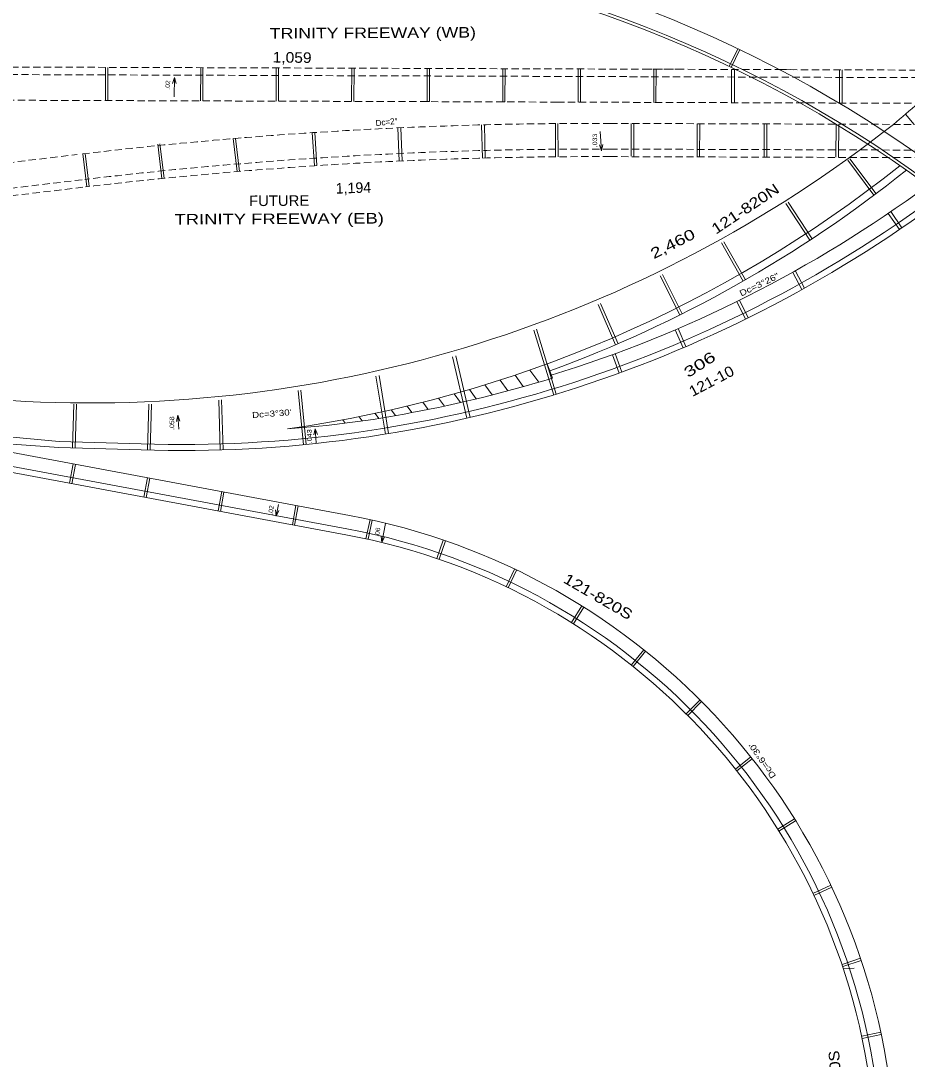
# Model space of a CAD drawing. Extents: x 2354993 to 2372084, y 6966390 to 6990057.
# Drawn here: x 2363006 to 2364180, y 6976742 to 6978118 of the extents above; entities that cross this region are included whole.
import ezdxf
from ezdxf.enums import TextEntityAlignment as Align

# ---------------------------------------------------------------- set-up
doc = ezdxf.new("R2010")
doc.units = 0
doc.header["$LTSCALE"] = 3.2
doc.linetypes.add('MEDIUM_DASHED', pattern=[4.5, 3, -1.5])
for name, color, linetype, lineweight in [('12', 7, 'Continuous', 13), ('13', 7, 'Continuous', 13), ('17', 7, 'Continuous', 13), ('19', 7, 'Continuous', 13), ('23', 7, 'Continuous', 13), ('5', 7, 'Continuous', 13), ('61', 7, 'Continuous', 13), ('7', 7, 'Continuous', 13)]:
    doc.layers.add(name, color=color, linetype=linetype, lineweight=lineweight)

msp = doc.modelspace()

# ---------------------------------------------------------------- linework, layer by layer
at = {"layer": '12'}
for p, q in [((2363943.892, 6978057.276), (2363955.166, 6978080.703)), ((2363946.596, 6978055.978), (2363957.869, 6978079.405)), ((2363117.932, 6978011.954), (2363118.08, 6978055.955)), ((2363120.931, 6978011.944), (2363121.079, 6978055.945)), ((2363244.03, 6978055.53), (2363243.881, 6978011.53)), ((2363247.029, 6978055.52), (2363246.881, 6978011.52)), ((2363344.03, 6978055.193), (2363343.881, 6978011.193)), ((2363347.029, 6978055.183), (2363346.88, 6978011.182)), ((2363444.028, 6978054.856), (2363443.88, 6978010.855)), ((2363447.028, 6978054.845), (2363446.879, 6978010.845)), ((2363544.028, 6978054.518), (2363543.88, 6978010.518)), ((2363547.027, 6978054.508), (2363546.879, 6978010.507)), ((2363644.027, 6978054.181), (2363643.878, 6978010.18)), ((2363647.026, 6978054.17), (2363646.878, 6978010.17)), ((2363743.878, 6978009.844), (2363744.027, 6978053.844)), ((2363747.026, 6978053.834), (2363744.027, 6978053.844)), ((2363746.877, 6978009.833), (2363747.026, 6978053.834)), ((2363844.027, 6978053.507), (2363843.878, 6978009.506)), ((2363847.026, 6978053.496), (2363846.877, 6978009.496)), ((2363947.025, 6978053.159), (2363946.876, 6978009.159)), ((2363951.025, 6978053.145), (2363950.876, 6978009.145)), ((2363546.879, 6978010.507), (2363543.88, 6978010.518)), ((2363643.878, 6978010.18), (2363646.878, 6978010.17)), ((2364046.876, 6978008.821), (2364043.877, 6978008.831)), ((2364177.285, 6977993.799), (2364188.905, 6977980.343)), ((2364154.496, 6977862.559), (2364169.167, 6977841.094)), ((2364157.799, 6977864.816), (2364172.47, 6977843.351)), ((2364028.251, 6977784.188), (2364040.203, 6977761.604)), ((2364031.787, 6977786.059), (2364043.738, 6977763.474)), ((2363957.495, 6977747.502), (2363969.04, 6977724.206)), ((2363953.911, 6977745.726), (2363965.456, 6977722.43)), ((2363872.441, 6977708.284), (2363882.716, 6977684.401)), ((2363876.115, 6977709.865), (2363886.39, 6977685.981)), ((2363789.168, 6977675.319), (2363798.086, 6977650.897)), ((2363792.926, 6977676.691), (2363801.844, 6977652.269))]:
    msp.add_line(p, q, dxfattribs=at)
at = {"layer": '17'}
for p, q in [((2363213.75, 6977595.134), (2363216.528, 6977587.302)), ((2363395.689, 6977577.258), (2363398.467, 6977569.426)), ((2363343.757, 6977461.575), (2363343.114, 6977469.86)), ((2363483.762, 6977426.498), (2363483.119, 6977434.783))]:
    msp.add_line(p, q, dxfattribs=at)
for points in [[(2363214.946, 6977576.421), (2363213.75, 6977595.134), (2363211.989, 6977587.01)], [(2363396.885, 6977558.545), (2363395.689, 6977577.258), (2363393.928, 6977569.134)], [(2363346.852, 6977476.819), (2363343.757, 6977461.575), (2363347.575, 6977468.951)], [(2363488.892, 6977451.764), (2363483.762, 6977426.498), (2363487.58, 6977433.874)]]:
    msp.add_lwpolyline(points, dxfattribs=at)
at = {"layer": '19'}
for p, q in [((2363209.28, 6978042.726), (2363211.427, 6978034.696)), ((2363774.866, 6977945.446), (2363772.047, 6977953.265))]:
    msp.add_line(p, q, dxfattribs=at)
for points in [[(2363208.858, 6978016.946), (2363209.28, 6978042.726), (2363206.875, 6978034.776)], [(2363773.102, 6977971.168), (2363774.866, 6977945.446), (2363776.589, 6977953.571)]]:
    msp.add_lwpolyline(points, dxfattribs=at)
at = {"layer": '23'}
msp.add_line((2364095.179, 6976861.879), (2364109.155, 6976862.696), dxfattribs=at)
at = {"layer": '5', "linetype": 'MEDIUM_DASHED'}
for p, q in [((2363881.241, 6978053.379), (2362958.761, 6978056.492)), ((2364028.375, 6978052.885), (2363826.78, 6978053.565)), ((2364725.162, 6978050.535), (2364010.427, 6978052.946)), ((2363836.954, 6978043.529), (2362958.726, 6978046.492)), ((2364037.424, 6978042.853), (2363803.238, 6978043.643)), ((2364727.772, 6978040.524), (2364029.265, 6978042.88)), ((2362958.612, 6978012.492), (2363716.295, 6978009.935)), ((2363715.928, 6978009.937), (2364096.849, 6978008.653)), ((2364089.244, 6978008.678), (2364762.775, 6978006.406)), ((2363786.467, 6977981.699), (2365246.775, 6977976.776)), ((2362801.702, 6977907.216), (2363080.587, 6977940.529)), ((2363786.352, 6977947.7), (2365246.66, 6977942.776)), ((2363786.319, 6977937.7), (2365246.626, 6977932.776)), ((2362805.732, 6977873.455), (2363090.394, 6977907.458)), ((2362806.918, 6977863.526), (2363091.58, 6977897.529))]:
    msp.add_line(p, q, dxfattribs=at)
at = {"layer": '5'}
for p, q in [((2363680.035, 6977654.95), (2363691.558, 6977638.881)), ((2363702.768, 6977663.093), (2363709.649, 6977644.314)), ((2363640.373, 6977641.618), (2363650.618, 6977627.332)), ((2363660.284, 6977648.172), (2363671.172, 6977632.99)), ((2363579.665, 6977623.315), (2363587.923, 6977611.799)), ((2363600.066, 6977629.186), (2363608.996, 6977616.733)), ((2363620.301, 6977635.288), (2363629.893, 6977621.912)), ((2363538.357, 6977612.279), (2363545.24, 6977602.681)), ((2363559.096, 6977617.678), (2363566.672, 6977607.113)), ((2363475.093, 6977597.54), (2363479.821, 6977590.946)), ((2363496.358, 6977602.206), (2363501.818, 6977594.592)), ((2363517.445, 6977607.12), (2363523.623, 6977598.505)), ((2363432.015, 6977588.971), (2363435.238, 6977584.476)), ((2363453.646, 6977593.127), (2363457.63, 6977587.572)), ((2363056.715, 6977560.454), (2362953.628, 6977569.627)), ((2363436.244, 6977436.841), (2362775.531, 6977559.85)), ((2363437.708, 6977444.706), (2362776.995, 6977567.714)), ((2362952.814, 6977559.66), (2363056.326, 6977552.462)), ((2363165.231, 6977557.069), (2363056.715, 6977560.454)), ((2363441.003, 6977462.402), (2362950.662, 6977553.691)), ((2363164.981, 6977549.073), (2363056.326, 6977552.462))]:
    msp.add_line(p, q, dxfattribs=at)
for centre, radius, start, end in [((2363244.672, 6976597.082), 1645.014, 38.12295, 103.3303), ((2363244.672, 6976597.082), 1623.014, 38.12295, 103.3303), ((2363244.672, 6976597.082), 1619.014, 38.12295, 103.3303), ((2363127.192, 6979233.99), 1625.022, 309.51957, 311.04051), ((2363097.562, 6979328.645), 1717.302, 266.49182, 308.27248), ((2363127.192, 6979233.99), 1673.022, 277.96238, 308.55257), ((2363127.192, 6979233.99), 1683.022, 290.12282, 308.67239), ((2363217.727, 6979240.251), 1666, 287.12386, 306.40449), ((2363217.727, 6979240.251), 1684, 268.21361, 306.58945), ((2363217.727, 6979240.251), 1692, 268.21361, 306.66787), ((2363215.437, 6979250.646), 1680.639, 280.56637, 287.10131), ((2363265.996, 6978936.147), 1362.225, 273.91247, 280.90154), ((2363278.934, 6976591.886), 885.473, 4.66908, 79.45368), ((2363278.934, 6976591.886), 867.473, 4.66908, 79.45368), ((2363278.934, 6976591.886), 859.473, 4.66908, 79.45368)]:
    msp.add_arc(centre, radius, start, end, dxfattribs=at)
at = {"layer": '5', "linetype": 'MEDIUM_DASHED'}
for radius in [5739.578, 5705.578, 5695.578]:
    msp.add_arc((2363767.116, 6972242.154), radius, 89.80682, 96.81171, dxfattribs=at)
at = {"layer": '61'}
for p, q in [((2364090.028, 6978052.677), (2364089.879, 6978008.658)), ((2364093.528, 6978052.666), (2364093.379, 6978008.646)), ((2363713.621, 6977981.484), (2363714.004, 6977937.486)), ((2363717.121, 6977981.514), (2363717.504, 6977937.516)), ((2363814.093, 6977981.606), (2363813.947, 6977938.091)), ((2363817.593, 6977981.595), (2363817.447, 6977938.079)), ((2363901.359, 6977981.312), (2363901.209, 6977936.808)), ((2363904.859, 6977981.3), (2363904.709, 6977936.797)), ((2363990.363, 6977981.289), (2363990.213, 6977937.012)), ((2363993.862, 6977981.277), (2363993.713, 6977937)), ((2363394.559, 6977925.534), (2363391.681, 6977969.44)), ((2363397.837, 6977925.748), (2363394.985, 6977969.656)), ((2363506.94, 6977931.787), (2363504.93, 6977975.741)), ((2363510.86, 6977931.964), (2363508.88, 6977975.92)), ((2363617.208, 6977935.759), (2363616.05, 6977979.744)), ((2363620.771, 6977935.852), (2363619.64, 6977979.837)), ((2364085.307, 6977980.692), (2364085.159, 6977936.968)), ((2364088.807, 6977980.68), (2364088.659, 6977936.957)), ((2363192.564, 6977908.679), (2363187.108, 6977954.356)), ((2363195.55, 6977908.98), (2363190.087, 6977954.711)), ((2363292.347, 6977917.91), (2363286.922, 6977961.609)), ((2363295.34, 6977918.159), (2363289.913, 6977961.86)), ((2363093.163, 6977897.717), (2363087.932, 6977941.511)), ((2363096.142, 6977898.072), (2363090.911, 6977941.866)), ((2364100.733, 6977932.869), (2364135.48, 6977886.429)), ((2364103.535, 6977934.966), (2364138.28, 6977888.529)), ((2364018.816, 6977875.423), (2364050.64, 6977826.933)), ((2364021.742, 6977877.343), (2364053.564, 6977828.856)), ((2363933.77, 6977823.27), (2363962.558, 6977772.919)), ((2363936.808, 6977825.007), (2363965.595, 6977774.659)), ((2363852.499, 6977779.81), (2363878.497, 6977727.967)), ((2363855.628, 6977781.379), (2363881.627, 6977729.533)), ((2363770.355, 6977741.659), (2363793.423, 6977688.448)), ((2363773.566, 6977743.051), (2363796.636, 6977689.837)), ((2363711.411, 6977621.871), (2363685.022, 6977707.712)), ((2363714.929, 6977622.952), (2363688.481, 6977708.981)), ((2363596.2, 6977591.123), (2363577.5, 6977672.606)), ((2363600.62, 6977592.144), (2363581.647, 6977673.808)), ((2363488.545, 6977570.065), (2363476.092, 6977646.865)), ((2363492.823, 6977570.764), (2363480.136, 6977647.759)), ((2363380.001, 6977556.05), (2363373.1, 6977627.681)), ((2363383.787, 6977556.419), (2363376.704, 6977628.237)), ((2363074.252, 6977551.903), (2363076.056, 6977609.772)), ((2363077.93, 6977551.788), (2363079.735, 6977609.661)), ((2363173.608, 6977548.826), (2363175.196, 6977609.677)), ((2363177.287, 6977548.73), (2363178.88, 6977609.79)), ((2363269.927, 6977549.056), (2363267.89, 6977615.07)), ((2363273.606, 6977549.17), (2363271.561, 6977615.393)), ((2363075.204, 6977530.505), (2363070.445, 6977504.944)), ((2363078.153, 6977529.955), (2363073.395, 6977504.395)), ((2363173.515, 6977512.202), (2363168.756, 6977486.641)), ((2363176.464, 6977511.652), (2363171.705, 6977486.092)), ((2363271.826, 6977493.898), (2363267.067, 6977468.338)), ((2363274.775, 6977493.349), (2363270.016, 6977467.789)), ((2363370.136, 6977475.595), (2363365.377, 6977450.035)), ((2363373.086, 6977475.046), (2363368.327, 6977449.486)), ((2363468.322, 6977456.869), (2363462.761, 6977431.471)), ((2363471.253, 6977456.228), (2363465.691, 6977430.824)), ((2363565.242, 6977429.795), (2363556.836, 6977405.192)), ((2363568.081, 6977428.825), (2363559.673, 6977404.217)), ((2363659.659, 6977391.331), (2363648.479, 6977367.857)), ((2363662.367, 6977390.041), (2363651.186, 6977366.563)), ((2363748.816, 6977342.408), (2363734.942, 6977320.413)), ((2363751.354, 6977340.808), (2363737.482, 6977318.817)), ((2363830.586, 6977284.528), (2363814.316, 6977264.241)), ((2363832.926, 6977282.651), (2363816.659, 6977262.368)), ((2363905.215, 6977217.854), (2363886.826, 6977199.474)), ((2363907.336, 6977215.732), (2363888.943, 6977197.348)), ((2363972.477, 6977142.405), (2363952.054, 6977126.307)), ((2363974.334, 6977140.049), (2363953.915, 6977123.954)), ((2364030.243, 6977060.509), (2364008.132, 6977046.821)), ((2364031.822, 6977057.958), (2364009.715, 6977044.273)), ((2364078.323, 6976972.741), (2364054.808, 6976961.635)), ((2364079.604, 6976970.028), (2364056.094, 6976958.925)), ((2364117.693, 6976875.712), (2364093.298, 6976867.549)), ((2364118.644, 6976872.867), (2364094.25, 6976864.704)), ((2364144.668, 6976777.834), (2364119.327, 6976772.48)), ((2364145.289, 6976774.898), (2364119.947, 6976769.545))]:
    msp.add_line(p, q, dxfattribs=at)

# ---------------------------------------------------------------- texts
at = {"layer": '13'}
for s, width, p in [('TRINITY FREEWAY (WB)', 1.25, (2363472.031, 6978094.727)), ('FUTURE', 1.05, (2363347.915, 6977872.36)), ('TRINITY FREEWAY (EB)', 1.3, (2363348.042, 6977848.361))]:
    msp.add_text(s, height=14, rotation=0.302, dxfattribs=dict(at, width=width)).set_placement(p, align=Align.CENTER)
for s, rotation, width, p in [('1,059', 359.244, 1.1, (2363339.209, 6978062.444)), ('121-820N', 33.735, 1.25, (2363926.23, 6977834.217)), ('2,460', 26.958, 1.35, (2363843.998, 6977801.699)), ('306', 32.958, 1.45, (2363889.516, 6977644.174)), ('121-10', 27.735, 1.1, (2363895.257, 6977619.276)), ('121-820S', 329.864, 1.25, (2363722.888, 6977374.271)), ('121-820S', 94.338, 1.15, (2364096.276, 6976660.824))]:
    msp.add_text(s, height=14, rotation=rotation, dxfattribs=dict(at, width=width)).set_placement(p)
msp.add_text('1,194', height=14, rotation=1.924, dxfattribs=at).set_placement((2363423.094, 6977888.59))
at = {"layer": '17'}
msp.add_text('Dc=2°', height=8, rotation=6.166, dxfattribs=at).set_placement((2363476.026, 6977978.017))
for s, height, rotation, width, p in [("Dc=3°30'", 7.999, 4.213, 1.2, (2363312.426, 6977591.343)), ('.058', 6, 89.81, 1.15, (2363208.875, 6977575.605)), ('.043', 6, 89.81, 1.2, (2363390.813, 6977557.729)), ('.02', 5.999, 83.33, 1.1, (2363339.446, 6977463.122)), ('.06', 5.999, 83.33, 1.1, (2363480.477, 6977433.853)), ("Dc=6°30'", 7.999, 124.053, 1.25, (2364006.248, 6977117.193))]:
    msp.add_text(s, height=height, rotation=rotation, dxfattribs=dict(at, width=width)).set_placement(p)
at = {"layer": '19'}
for s, rotation, width, p in [('.02', 85.853, 1.1, (2363202.789, 6978026.231)), ('.033', 90.548, 1.15, (2363769.037, 6977950.136))]:
    msp.add_text(s, height=6, rotation=rotation, dxfattribs=dict(at, width=width)).set_placement(p)
at = {"layer": '7', "width": 1.25}
msp.add_text('Dc=3°26"', height=8, rotation=25.846, dxfattribs=at).set_placement((2363959.887, 6977752.301))

doc.saveas('drawing.dxf')
